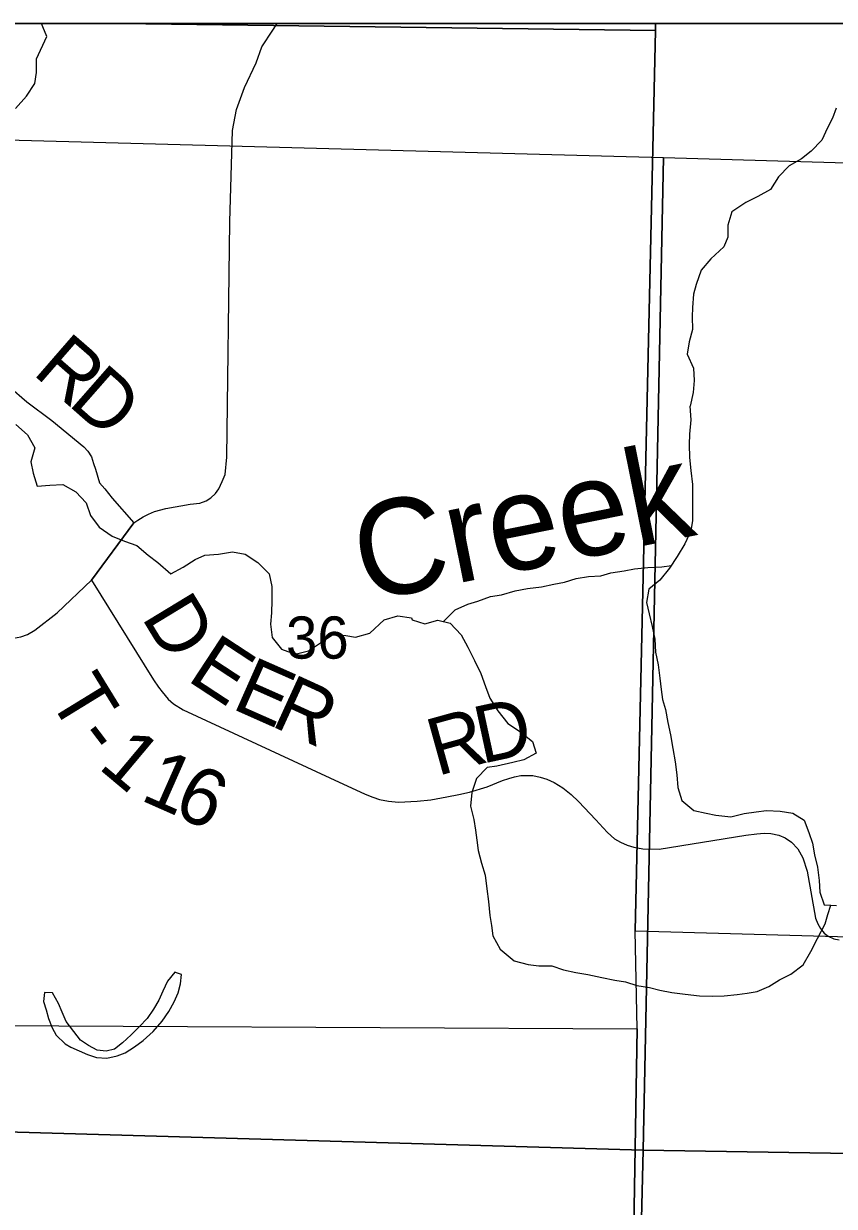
# Model space of a CAD drawing. Extents: x -19.9 to 41.9, y 0 to 32.3.
# Drawn here: x 4.462 to 5.266, y 19.727 to 20.9 of the extents above; entities that cross this region are included whole.
import ezdxf

# ---------------------------------------------------------------- set-up
doc = ezdxf.new("R2010")
doc.units = 0
for name, color, linetype in [('GM_X_Corporation', 7, 'Continuous'), ('GM_X_County_Road', 7, 'Continuous'), ('GM_X_Major_Lake', 7, 'Continuous'), ('GM_X_Major_River', 7, 'Continuous'), ('GM_X_Major_River_Text', 7, 'Continuous'), ('GM_X_Minor_Lake', 7, 'Continuous'), ('GM_X_Minor_River', 7, 'Continuous'), ('GM_X_Section', 7, 'Continuous'), ('GM_X_Section_Text', 7, 'Continuous'), ('GM_X_Township_Road', 7, 'Continuous'), ('GM_X_Township_Road_Text', 7, 'Continuous'), ('SH_Data', 7, 'Continuous')]:
    doc.layers.add(name, color=color, linetype=linetype)

msp = doc.modelspace()

# ---------------------------------------------------------------- linework, layer by layer
at = {"layer": 'GM_X_Corporation'}
for points in [[(8.9, 17.8974), (8.9, 20.9), (2.1, 20.9), (2.1, 17.918), (2.4715, 17.9106), (2.973, 17.9007), (3.7505, 17.884), (3.984, 17.879), (4.2613, 17.8672), (4.9169, 17.8392), (5.0192, 17.8403), (5.0257, 17.9637), (5.4954, 17.9559), (5.761, 17.9543), (5.9048, 17.9534), (6.2397, 17.9517), (6.2497, 17.9517), (6.3069, 17.9505), (6.7, 17.9422), (6.9468, 17.937), (7.3858, 17.9277), (7.5529, 17.9242), (7.9072, 17.9171)], [(4.5578, 20.9), (4.0724, 20.9), (4.0503, 19.9079), (5.0703, 19.9026), (5.0685, 20), (5.0885, 20.8933)], [(5.0886, 20.9), (4.5578, 20.9), (5.0885, 20.8933)], [(5.9372, 20.9), (5.0886, 20.9), (5.0885, 20.8933), (5.0685, 20), (5.9183, 19.976)], [(5.0685, 20), (5.9183, 19.976), (5.8941, 18.9811), (5.0551, 18.9965), (5.0703, 19.9026)], [(4.0503, 19.9079), (5.0703, 19.9026), (5.0551, 18.9965), (5.0537, 18.8813), (4.0319, 18.9009)]]:
    msp.add_lwpolyline(points, close=True, dxfattribs=at)
msp.add_lwpolyline([(2.973, 17.9007), (3.7505, 17.884), (3.984, 17.879), (4.2613, 17.8672), (4.9169, 17.8392), (5.0192, 17.8403), (5.0257, 17.9637), (5.4954, 17.9559), (5.761, 17.9543), (5.9048, 17.9534), (6.2397, 17.9517), (6.2497, 17.9517), (6.3069, 17.9505), (6.7, 17.9422), (6.9468, 17.937), (7.3858, 17.9277), (7.5529, 17.9242), (7.9072, 17.9171), (7.9208, 18.3004), (7.9387, 18.9418), (7.9433, 19.1981), (7.9567, 19.9408), (7.9833, 20.9), (2.1, 20.9)], dxfattribs=at)
at = {"layer": 'GM_X_County_Road'}
msp.add_line((4.529, 20.3478), (4.5711, 20.4046), dxfattribs=at)
for points in [[(4.5711, 20.4046), (4.5752, 20.4075), (4.5804, 20.4108), (4.5857, 20.4135), (4.5915, 20.4161), (4.6029, 20.4191), (4.627, 20.4234), (4.6364, 20.4244), (4.6427, 20.4265), (4.6475, 20.4294), (4.652, 20.4337), (4.6553, 20.4386), (4.6588, 20.4456), (4.6617, 20.4527), (4.6634, 20.47), (4.6662, 20.7034), (4.6688, 20.7939), (4.673, 20.8149), (4.681, 20.8367), (4.6924, 20.8612), (4.6982, 20.8769), (4.7089, 20.8934), (4.7134, 20.9)], [(4.2286, 19.8611), (4.2303, 20.0199), (4.2305, 20.0932), (4.2301, 20.172), (4.2294, 20.2206), (4.2313, 20.2385), (4.2335, 20.2529), (4.2365, 20.2644), (4.2423, 20.281), (4.248, 20.2864), (4.2564, 20.2913), (4.264, 20.2926), (4.2714, 20.2927), (4.2841, 20.293), (4.3257, 20.2932), (4.4349, 20.2907), (4.4439, 20.2907), (4.4516, 20.2903), (4.4589, 20.2915), (4.4657, 20.294), (4.4728, 20.2984), (4.495, 20.3155), (4.529, 20.3478)]]:
    msp.add_lwpolyline(points, dxfattribs=at)
at = {"layer": 'GM_X_Major_Lake'}
for points in [[(5.2679, 20.8162), (5.2642, 20.8062), (5.2591, 20.7967), (5.2536, 20.7844), (5.2431, 20.7736), (5.2334, 20.7659), (5.2213, 20.7589), (5.2105, 20.7481), (5.2027, 20.7354), (5.1899, 20.7284), (5.1782, 20.7225), (5.1643, 20.7132), (5.1603, 20.7002), (5.1602, 20.6881), (5.1565, 20.6785), (5.1434, 20.6666), (5.1337, 20.6554), (5.129, 20.6413), (5.1261, 20.6317), (5.1252, 20.6185), (5.125, 20.609), (5.1252, 20.5965), (5.122, 20.5843), (5.1199, 20.5721), (5.1262, 20.5582), (5.1268, 20.546), (5.1259, 20.5339), (5.123, 20.5205)], [(5.123, 20.5205), (5.1227, 20.5205), (5.1237, 20.5069), (5.1224, 20.4928), (5.1218, 20.4826), (5.1224, 20.4697), (5.1237, 20.4568), (5.1251, 20.4428), (5.1253, 20.4299), (5.1252, 20.417), (5.1253, 20.4072), (5.1236, 20.3969), (5.1177, 20.3839), (5.11, 20.3712), (5.1025, 20.3597), (5.0929, 20.3478), (5.082, 20.3389), (5.0795, 20.3256), (5.0824, 20.3143), (5.0853, 20.3018), (5.0878, 20.2893), (5.0884, 20.2764), (5.0912, 20.264), (5.093, 20.2507), (5.0943, 20.2393), (5.0956, 20.2295), (5.0984, 20.2197), (5.1009, 20.2068), (5.1034, 20.1944), (5.1059, 20.1807), (5.108, 20.1675), (5.1098, 20.1546), (5.1107, 20.1421), (5.1148, 20.1293), (5.1267, 20.1192), (5.1389, 20.1168), (5.1485, 20.1147), (5.1633, 20.113), (5.1766, 20.1163), (5.1883, 20.118), (5.1986, 20.1193), (5.2123, 20.1188), (5.2248, 20.1167), (5.236, 20.1097), (5.2407, 20.0976), (5.2443, 20.087), (5.2464, 20.0753), (5.2493, 20.0632), (5.251, 20.05), (5.2516, 20.0382), (5.256, 20.0258), (5.2624, 20.0255)], [(5.2624, 20.0255), (5.2682, 20.0252)]]:
    msp.add_lwpolyline(points, dxfattribs=at)
at = {"layer": 'GM_X_Major_River'}
for points in [[(4.4539, 20.5023), (4.4655, 20.4919), (4.4729, 20.4791), (4.469, 20.4654), (4.4711, 20.454), (4.4751, 20.4412), (4.4876, 20.4422), (4.5005, 20.4427), (4.5136, 20.4354), (4.5237, 20.4245), (4.528, 20.4121), (4.5366, 20.4005), (4.5497, 20.3916), (4.5619, 20.3865), (4.5742, 20.3821), (4.5853, 20.3728), (4.595, 20.3654), (4.6077, 20.3542), (4.6201, 20.3609), (4.6318, 20.3683), (4.6416, 20.3726), (4.6549, 20.3736), (4.6689, 20.3761), (4.6815, 20.3737), (4.6942, 20.3655), (4.7054, 20.3543), (4.7079, 20.3415), (4.7081, 20.3278), (4.7076, 20.3153), (4.7066, 20.3043), (4.7084, 20.291), (4.7177, 20.2794), (4.7311, 20.2743), (4.7443, 20.2776), (4.7563, 20.2858), (4.7691, 20.2943), (4.7813, 20.293), (4.7908, 20.2913), (4.8052, 20.2953), (4.8194, 20.3084), (4.8331, 20.3124), (4.8464, 20.3104)], [(4.8464, 20.3104), (4.8472, 20.3085), (4.8598, 20.3045), (4.8727, 20.3082), (4.8849, 20.3053), (4.8957, 20.2937), (4.9024, 20.2813), (4.9091, 20.2682), (4.9154, 20.2554), (4.9198, 20.2422), (4.9241, 20.2309), (4.932, 20.2181), (4.942, 20.2057), (4.9536, 20.198), (4.9667, 20.1879), (4.9703, 20.1762), (4.9579, 20.1696), (4.9469, 20.1671), (4.9313, 20.1634), (4.9215, 20.1621), (4.911, 20.151), (4.9063, 20.1372), (4.905, 20.1236), (4.9083, 20.1103), (4.91, 20.0997), (4.9113, 20.0899), (4.9126, 20.0797), (4.9158, 20.0672), (4.9195, 20.0551), (4.9212, 20.0415), (4.9229, 20.029), (4.9243, 20.015), (4.926, 20.0052), (4.9273, 19.9949), (4.9344, 19.9818), (4.9483, 19.9702), (4.9624, 19.9667), (4.9727, 19.9653), (4.9856, 19.9652), (4.9974, 19.9612), (5.0096, 19.9587), (5.0215, 19.9567), (5.0352, 19.9538), (5.0482, 19.951), (5.0588, 19.9493), (5.0699, 19.9457), (5.0825, 19.9436), (5.0928, 19.9411), (5.1046, 19.9387), (5.118, 19.937), (5.1321, 19.9353), (5.145, 19.9352), (5.1568, 19.9354), (5.1697, 19.9367), (5.1795, 19.938), (5.1894, 19.9397), (5.2011, 19.9448), (5.2116, 19.9514), (5.2229, 19.9569), (5.2349, 19.9662), (5.2427, 19.9796), (5.2493, 19.9923), (5.2567, 20.0068), (5.2596, 20.0163), (5.2624, 20.0255)]]:
    msp.add_lwpolyline(points, dxfattribs=at)
at = {"layer": 'GM_X_Minor_Lake'}
for points in [[(4.4903, 19.9383), (4.4823, 19.9387), (4.4816, 19.9299), (4.484, 19.9216), (4.4863, 19.9129), (4.4902, 19.9038), (4.4941, 19.8963), (4.5029, 19.888), (4.5086, 19.8846), (4.517, 19.8809), (4.525, 19.8772), (4.5341, 19.8742), (4.5444, 19.8736), (4.5546, 19.8759), (4.5626, 19.879), (4.5716, 19.8848), (4.5803, 19.8913), (4.5901, 19.9001), (4.5991, 19.9104), (4.6059, 19.92), (4.6111, 19.9295), (4.6149, 19.9383), (4.6174, 19.9474), (4.6185, 19.9565), (4.6143, 19.9581)], [(4.6143, 19.9581), (4.6116, 19.9591), (4.6045, 19.9499), (4.6, 19.94), (4.5959, 19.9313), (4.5907, 19.9221), (4.5843, 19.913), (4.5768, 19.9049), (4.5685, 19.8969), (4.5598, 19.8889), (4.5519, 19.8827), (4.5436, 19.8804), (4.5348, 19.8814), (4.5261, 19.8863), (4.518, 19.8915), (4.5115, 19.9002), (4.5038, 19.91), (4.4999, 19.9191), (4.4964, 19.9278), (4.4903, 19.9383)]]:
    msp.add_lwpolyline(points, dxfattribs=at)
at = {"layer": 'GM_X_Minor_River'}
for points in [[(4.4537, 20.8159), (4.4646, 20.8282), (4.4728, 20.8407), (4.4746, 20.8514), (4.4745, 20.865), (4.4849, 20.8871), (4.4807, 20.897), (4.4796, 20.9)], [(4.8783, 20.3068), (4.8899, 20.3185), (4.9024, 20.3239), (4.9123, 20.327), (4.9248, 20.3317), (4.9358, 20.3333), (4.9494, 20.3372), (4.9615, 20.3396), (4.9756, 20.3412), (4.9877, 20.344), (4.9983, 20.3459), (5.0097, 20.3495), (5.0222, 20.3515), (5.0343, 20.3523), (5.0442, 20.3551), (5.0575, 20.3571), (5.0677, 20.359), (5.081, 20.3603), (5.0947, 20.3612), (5.1043, 20.3625)]]:
    msp.add_lwpolyline(points, dxfattribs=at)
at = {"layer": 'GM_X_Section'}
for points in [[(4.2277, 19.8611), (4.2465, 20.6998), (4.2479, 20.79), (5.0965, 20.7671), (5.0763, 19.7825), (4.3977, 19.8017)], [(4.3977, 19.8017), (5.0763, 19.7825), (5.0521, 18.7876), (4.2131, 18.8031), (4.2222, 19.3423)]]:
    msp.add_lwpolyline(points, dxfattribs=at)
for points in [[(5.0965, 20.7671), (6.1184, 20.7376), (6.0885, 19.7661), (5.0763, 19.7825)], [(5.0763, 19.7825), (6.0885, 19.7661), (6.0716, 18.7702), (5.0521, 18.7876)]]:
    msp.add_lwpolyline(points, close=True, dxfattribs=at)
at = {"layer": 'GM_X_Township_Road'}
msp.add_line((4.5711, 20.4046), (4.529, 20.3478), dxfattribs=at)
for points in [[(4.4474, 20.54), (4.4648, 20.5249), (4.4897, 20.5062), (4.5215, 20.48), (4.5255, 20.4758), (4.5292, 20.4701), (4.5311, 20.4636), (4.5331, 20.4581), (4.5369, 20.4445), (4.5424, 20.4385), (4.5495, 20.4291), (4.5711, 20.4046)], [(4.529, 20.3478), (4.5907, 20.2491), (4.5955, 20.2416), (4.5991, 20.2372), (4.605, 20.2299), (4.6105, 20.2253), (4.62, 20.2191), (4.7656, 20.1519), (4.8004, 20.1355), (4.8081, 20.1326), (4.8149, 20.1304), (4.8236, 20.1287), (4.8337, 20.1275), (4.8521, 20.1287), (4.8656, 20.13), (4.8817, 20.1328), (4.8935, 20.1351), (4.9042, 20.1375), (4.9215, 20.1427), (4.9368, 20.1491), (4.9431, 20.151), (4.9487, 20.1528), (4.9551, 20.154), (4.9612, 20.1542), (4.967, 20.154), (4.9741, 20.1525), (4.9806, 20.1503), (4.9879, 20.147), (4.9965, 20.1417), (5.0049, 20.1352), (5.0122, 20.1283), (5.0292, 20.1102), (5.0367, 20.1022), (5.041, 20.0975), (5.048, 20.0912), (5.0539, 20.088), (5.0605, 20.085), (5.0672, 20.0829), (5.0761, 20.0813), (5.0923, 20.081), (5.1783, 20.0947), (5.189, 20.0961), (5.1963, 20.0968), (5.203, 20.0964), (5.2109, 20.095), (5.2173, 20.0922), (5.2233, 20.088), (5.2296, 20.0812), (5.2347, 20.0724), (5.2389, 20.0593), (5.2473, 20.0126), (5.2496, 20.0069), (5.2521, 20.0023), (5.2558, 19.9977), (5.2598, 19.9947), (5.2655, 19.9921), (5.2709, 19.9911)]]:
    msp.add_lwpolyline(points, dxfattribs=at)
at = {"layer": 'SH_Data'}
msp.add_line((2.1, 20.9), (8.9, 20.9), dxfattribs=at)

# ---------------------------------------------------------------- texts
at = {"layer": 'GM_X_Major_River_Text'}
msp.add_text('Creek', height=0.0947, rotation=11.4091, dxfattribs=at).set_placement((4.7997, 20.326))
at = {"layer": 'GM_X_Section_Text'}
msp.add_text('36', height=0.04186, rotation=0, dxfattribs=at).set_placement((4.722, 20.27))
at = {"layer": 'GM_X_Township_Road_Text'}
for s, rotation, p in [('R', 319.005, (4.4695, 20.553)), ('D', 318.6989, (4.5047, 20.5224)), ('D', 301.2686, (4.578, 20.3112)), ('E', 326.7438, (4.6226, 20.2491)), ('E', 336.0812, (4.6669, 20.221)), ('T', 301.537, (4.4853, 20.2319)), ('R', 335.3886, (4.7056, 20.2039)), ('R', 15.4961, (4.8719, 20.1533)), ('D', 12.208, (4.916, 20.1655)), ('-', 307.2158, (4.511, 20.1906)), ('1', 320.0157, (4.5346, 20.162)), ('1', 336.1542, (4.5762, 20.1303)), ('6', 335.2645, (4.608, 20.1163))]:
    msp.add_text(s, height=0.0568, rotation=rotation, dxfattribs=at).set_placement(p)

doc.saveas('drawing.dxf')
